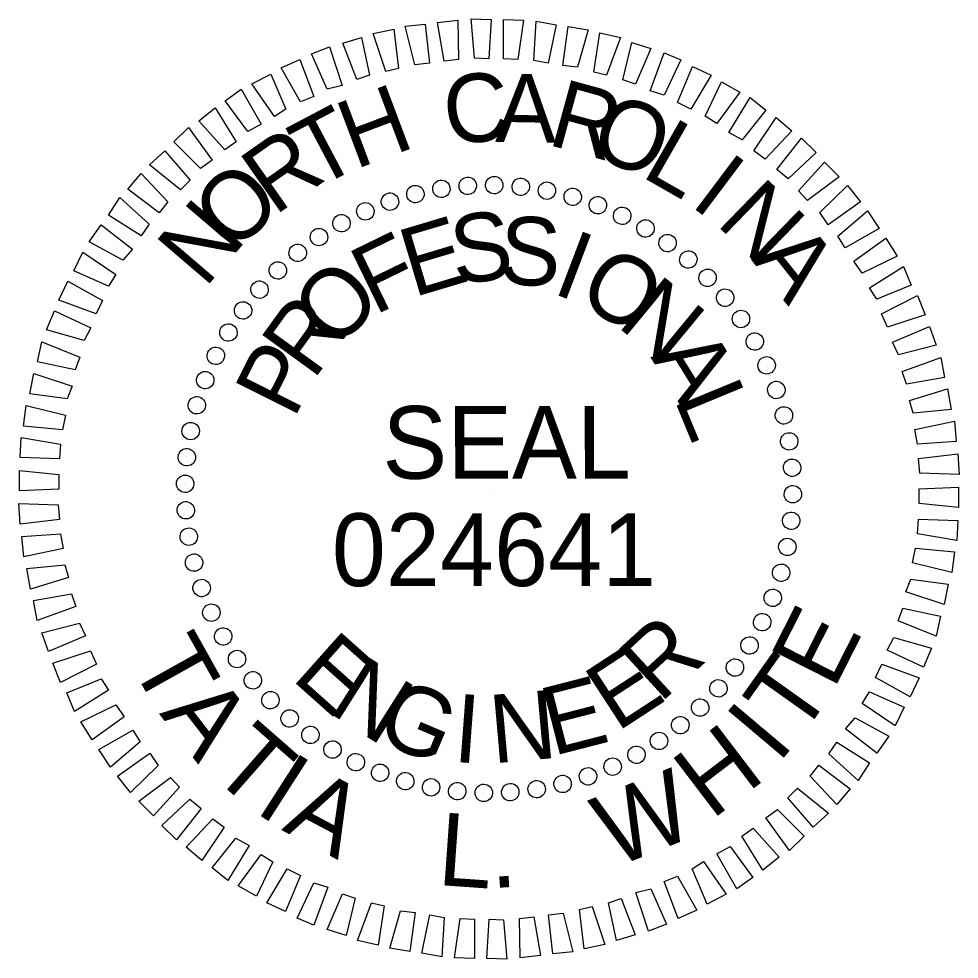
# Model space of a CAD drawing. Extents: x 573468 to 580768, y -57414 to -51768.
# Drawn here: x 580590.4 to 580668, y -53157.1 to -53079.5 of the extents above; entities that cross this region are included whole.
import ezdxf

# ---------------------------------------------------------------- set-up
doc = ezdxf.new("R2010")
doc.units = 0
doc.layers.add('Sheet Professional Seal CELL', color=7, linetype='Continuous')

msp = doc.modelspace()

# ---------------------------------------------------------------- linework, layer by layer
at = {"layer": 'Sheet Professional Seal CELL'}
for p, q in [((580627.458, -53093.227), (580627.458, -53093.227)), ((580629.658, -53093.176), (580629.658, -53093.176)), ((580631.858, -53093.325), (580631.858, -53093.325)), ((580623.108, -53093.928), (580623.108, -53093.928)), ((580625.308, -53093.527), (580625.308, -53093.527)), ((580634.008, -53093.675), (580634.008, -53093.675)), ((580636.108, -53094.124), (580636.108, -53094.124)), ((580621.008, -53094.528), (580621.008, -53094.528)), ((580638.208, -53094.824), (580638.208, -53094.824)), ((580619.008, -53095.329), (580619.008, -53095.329)), ((580640.208, -53095.723), (580640.208, -53095.723)), ((580617.059, -53096.329), (580617.059, -53096.329)), ((580642.159, -53096.723), (580642.159, -53096.723)), ((580615.159, -53097.48), (580615.159, -53097.48)), ((580643.959, -53097.972), (580643.959, -53097.972)), ((580613.409, -53098.73), (580613.409, -53098.73)), ((580645.709, -53099.322), (580645.709, -53099.322)), ((580611.76, -53100.23), (580611.76, -53100.23)), ((580647.26, -53100.822), (580647.26, -53100.822)), ((580610.26, -53101.781), (580610.26, -53101.781)), ((580648.76, -53102.471), (580648.76, -53102.471)), ((580608.91, -53103.531), (580608.91, -53103.531)), ((580650.011, -53104.221), (580650.011, -53104.221)), ((580607.661, -53105.331), (580607.661, -53105.331)), ((580651.161, -53106.121), (580651.161, -53106.121)), ((580606.661, -53107.282), (580606.661, -53107.282)), ((580652.162, -53108.07), (580652.162, -53108.07)), ((580605.762, -53109.282), (580605.762, -53109.282)), ((580652.962, -53110.07), (580652.962, -53110.07)), ((580605.062, -53111.382), (580605.062, -53111.382)), ((580653.563, -53112.17), (580653.563, -53112.17)), ((580604.613, -53113.482), (580604.613, -53113.482)), ((580653.963, -53114.37), (580653.963, -53114.37)), ((580604.263, -53115.632), (580604.263, -53115.632)), ((580654.264, -53116.52), (580654.264, -53116.52)), ((580604.114, -53117.832), (580604.114, -53117.832)), ((580629.214, -53118.276), (580629.214, -53118.276)), ((580654.314, -53118.72), (580654.314, -53118.72)), ((580604.165, -53120.032), (580604.165, -53120.032)), ((580654.165, -53120.92), (580654.165, -53120.92)), ((580604.465, -53122.182), (580604.465, -53122.182)), ((580653.815, -53123.07), (580653.815, -53123.07)), ((580604.866, -53124.382), (580604.866, -53124.382)), ((580653.366, -53125.17), (580653.366, -53125.17)), ((580605.466, -53126.482), (580605.466, -53126.482)), ((580652.666, -53127.27), (580652.666, -53127.27)), ((580606.267, -53128.482), (580606.267, -53128.482)), ((580651.767, -53129.27), (580651.767, -53129.27)), ((580607.267, -53130.432), (580607.267, -53130.432)), ((580650.767, -53131.221), (580650.767, -53131.221)), ((580608.418, -53132.331), (580608.418, -53132.331)), ((580649.518, -53133.021), (580649.518, -53133.021)), ((580609.668, -53134.081), (580609.668, -53134.081)), ((580648.168, -53134.771), (580648.168, -53134.771)), ((580611.168, -53135.731), (580611.168, -53135.731)), ((580646.669, -53136.322), (580646.669, -53136.322)), ((580612.719, -53137.23), (580612.719, -53137.23)), ((580645.019, -53137.822), (580645.019, -53137.822)), ((580614.469, -53138.58), (580614.469, -53138.58)), ((580643.269, -53139.073), (580643.269, -53139.073)), ((580616.27, -53139.829), (580616.27, -53139.829)), ((580618.22, -53140.829), (580618.22, -53140.829)), ((580641.37, -53140.223), (580641.37, -53140.223)), ((580639.42, -53141.224), (580639.42, -53141.224)), ((580620.22, -53141.728), (580620.22, -53141.728)), ((580637.42, -53142.024), (580637.42, -53142.024)), ((580622.32, -53142.428), (580622.32, -53142.428)), ((580624.42, -53142.877), (580624.42, -53142.877)), ((580633.12, -53143.025), (580633.12, -53143.025)), ((580635.32, -53142.625), (580635.32, -53142.625)), ((580626.57, -53143.227), (580626.57, -53143.227)), ((580628.77, -53143.376), (580628.77, -53143.376)), ((580630.97, -53143.326), (580630.97, -53143.326))]:
    msp.add_line(p, q, dxfattribs=at)
for points in [[(580628.005, -53082.726), (580627.754, -53079.476), (580629.404, -53079.526), (580629.205, -53082.776)], [(580630.405, -53082.776), (580630.404, -53079.526), (580632.054, -53079.575), (580631.605, -53082.825)], [(580623.105, -53083.278), (580622.305, -53080.078), (580623.955, -53079.927), (580624.305, -53083.127)], [(580625.505, -53082.977), (580624.955, -53079.777), (580626.654, -53079.577), (580626.705, -53082.827)], [(580632.905, -53082.925), (580633.104, -53079.675), (580634.755, -53079.975), (580634.105, -53083.125)], [(580635.305, -53083.325), (580635.755, -53080.124), (580637.405, -53080.374), (580636.505, -53083.474)], [(580618.306, -53084.479), (580617.155, -53081.479), (580618.705, -53081.029), (580619.356, -53084.129)], [(580620.706, -53083.828), (580619.655, -53080.678), (580621.355, -53080.328), (580621.755, -53083.578)], [(580637.856, -53083.874), (580638.355, -53080.624), (580640.055, -53081.023), (580638.906, -53084.124)], [(580615.856, -53085.279), (580614.555, -53082.38), (580616.055, -53081.779), (580617.106, -53084.979)], [(580640.256, -53084.523), (580641.005, -53081.423), (580642.555, -53081.923), (580641.306, -53084.873)], [(580642.506, -53085.423), (580643.655, -53082.272), (580645.055, -53082.872), (580643.656, -53085.772)], [(580613.656, -53086.33), (580612.055, -53083.53), (580613.605, -53082.83), (580614.756, -53085.88)], [(580611.506, -53087.531), (580609.656, -53084.831), (580611.206, -53084.031), (580612.456, -53086.93)], [(580644.756, -53086.372), (580646.005, -53083.422), (580647.556, -53084.122), (580645.856, -53086.922)], [(580647.056, -53087.522), (580648.406, -53084.671), (580649.906, -53085.521), (580648.007, -53088.121)], [(580609.307, -53088.781), (580607.456, -53086.232), (580608.756, -53085.281), (580610.407, -53088.181)], [(580649.007, -53088.871), (580650.756, -53085.971), (580652.056, -53087.02), (580650.107, -53089.471)], [(580607.407, -53090.282), (580605.257, -53087.882), (580606.606, -53086.832), (580608.357, -53089.631)], [(580651.057, -53090.371), (580652.906, -53087.62), (580654.207, -53088.72), (580652.007, -53091.07)], [(580605.408, -53091.832), (580603.207, -53089.633), (580604.407, -53088.432), (580606.357, -53091.132)], [(580652.958, -53091.92), (580655.007, -53089.32), (580656.207, -53090.519), (580653.908, -53092.67)], [(580603.758, -53093.582), (580601.207, -53091.533), (580602.457, -53090.383), (580604.558, -53092.782)], [(580654.758, -53093.67), (580656.907, -53091.319), (580658.108, -53092.519), (580655.508, -53094.47)], [(580602.008, -53095.483), (580599.408, -53093.534), (580600.508, -53092.233), (580602.708, -53094.583)], [(580656.508, -53095.469), (580658.808, -53093.219), (580659.858, -53094.568), (580657.209, -53096.469)], [(580600.509, -53097.383), (580597.808, -53095.684), (580598.758, -53094.234), (580601.159, -53096.433)], [(580658.009, -53097.419), (580660.458, -53095.318), (580661.409, -53096.768), (580658.609, -53098.369)], [(580599.009, -53099.384), (580596.209, -53097.884), (580597.209, -53096.484), (580599.809, -53098.483)], [(580659.309, -53099.469), (580661.959, -53097.568), (580662.909, -53099.068), (580660.01, -53100.468)], [(580597.81, -53101.534), (580594.96, -53100.285), (580595.709, -53098.734), (580598.41, -53100.584)], [(580660.61, -53101.668), (580663.41, -53099.918), (580664.06, -53101.467), (580661.21, -53102.618)], [(580596.811, -53103.834), (580593.71, -53102.685), (580594.46, -53101.135), (580597.31, -53102.734)], [(580661.611, -53103.818), (580664.56, -53102.317), (580665.211, -53103.917), (580662.111, -53104.918)], [(580595.811, -53106.034), (580592.711, -53105.135), (580593.36, -53103.585), (580596.361, -53104.984)], [(580662.511, -53106.168), (580665.561, -53104.867), (580666.111, -53106.417), (580663.011, -53107.218)], [(580595.062, -53108.435), (580591.962, -53107.785), (580592.311, -53106.135), (580595.461, -53107.385)], [(580663.312, -53108.568), (580666.511, -53107.417), (580666.812, -53109.067), (580663.662, -53109.617)], [(580594.412, -53110.835), (580591.312, -53110.436), (580591.662, -53108.735), (580594.812, -53109.785)], [(580663.912, -53110.967), (580667.062, -53110.017), (580667.362, -53111.717), (580664.213, -53112.017)], [(580594.013, -53113.385), (580590.813, -53113.086), (580591.012, -53111.386), (580594.263, -53112.185)], [(580664.363, -53113.367), (580667.613, -53112.666), (580667.763, -53114.366), (580664.563, -53114.567)], [(580593.764, -53115.785), (580590.513, -53115.686), (580590.613, -53114.036), (580593.863, -53114.585)], [(580664.664, -53115.767), (580667.913, -53115.366), (580668.014, -53117.066), (580664.764, -53116.967)], [(580593.714, -53118.285), (580590.464, -53118.436), (580590.464, -53116.736), (580593.714, -53117.085)], [(580664.714, -53118.267), (580667.964, -53118.116), (580667.965, -53119.816), (580664.714, -53119.467)], [(580593.765, -53120.785), (580590.515, -53121.186), (580590.414, -53119.486), (580593.664, -53119.585)], [(580664.665, -53120.767), (580667.915, -53120.866), (580667.815, -53122.516), (580664.565, -53121.967)], [(580594.065, -53123.185), (580590.816, -53123.886), (580590.665, -53122.186), (580593.865, -53121.985)], [(580664.415, -53123.167), (580667.615, -53123.466), (580667.416, -53125.167), (580664.166, -53124.367)], [(580594.516, -53125.585), (580591.366, -53126.536), (580591.066, -53124.836), (580594.216, -53124.535)], [(580664.016, -53125.717), (580667.116, -53126.117), (580666.767, -53127.817), (580663.616, -53126.767)], [(580595.117, -53127.985), (580591.917, -53129.135), (580591.616, -53127.485), (580594.766, -53126.935)], [(580663.367, -53128.118), (580666.467, -53128.767), (580666.117, -53130.417), (580662.967, -53129.168)], [(580595.917, -53130.384), (580592.867, -53131.685), (580592.317, -53130.135), (580595.417, -53129.335)], [(580662.617, -53130.518), (580665.717, -53131.417), (580665.068, -53132.967), (580662.067, -53131.568)], [(580596.818, -53132.734), (580593.868, -53134.235), (580593.218, -53132.635), (580596.317, -53131.634)], [(580661.618, -53132.718), (580664.718, -53133.867), (580663.968, -53135.417), (580661.118, -53133.818)], [(580597.818, -53134.884), (580595.019, -53136.635), (580594.368, -53135.085), (580597.218, -53133.934)], [(580660.618, -53135.018), (580663.469, -53136.268), (580662.719, -53137.818), (580660.019, -53135.968)], [(580599.119, -53137.084), (580596.469, -53138.984), (580595.519, -53137.485), (580598.419, -53136.084)], [(580659.419, -53137.169), (580662.219, -53138.668), (580661.22, -53140.068), (580658.619, -53138.069)], [(580600.419, -53139.133), (580597.97, -53141.234), (580597.02, -53139.784), (580599.819, -53138.183)], [(580657.919, -53139.169), (580660.62, -53140.868), (580659.67, -53142.318), (580657.27, -53140.119)], [(580601.92, -53141.083), (580599.62, -53143.333), (580598.57, -53141.984), (580601.22, -53140.083)], [(580656.42, -53141.069), (580659.02, -53143.019), (580657.921, -53144.319), (580655.72, -53141.969)], [(580603.67, -53142.882), (580601.521, -53145.233), (580600.321, -53144.033), (580602.92, -53142.083)], [(580654.67, -53142.97), (580657.221, -53145.019), (580655.971, -53146.169), (580653.871, -53143.77)], [(580605.471, -53144.632), (580603.421, -53147.233), (580602.221, -53146.033), (580604.521, -53143.882)], [(580653.021, -53144.72), (580655.221, -53146.92), (580654.022, -53148.12), (580652.071, -53145.42)], [(580607.371, -53146.182), (580605.522, -53148.932), (580604.222, -53147.832), (580606.421, -53145.482)], [(580651.021, -53146.271), (580653.172, -53148.67), (580651.822, -53149.72), (580650.071, -53146.921)], [(580609.421, -53147.681), (580607.672, -53150.581), (580606.372, -53149.532), (580608.321, -53147.081)], [(580649.122, -53147.771), (580650.972, -53150.321), (580649.672, -53151.271), (580648.022, -53148.371)], [(580611.372, -53149.031), (580610.023, -53151.881), (580608.522, -53151.031), (580610.422, -53148.431)], [(580646.922, -53149.022), (580648.772, -53151.721), (580647.223, -53152.522), (580645.972, -53149.622)], [(580613.672, -53150.18), (580612.423, -53153.13), (580610.873, -53152.431), (580612.572, -53149.63)], [(580615.922, -53151.129), (580614.773, -53154.28), (580613.373, -53153.68), (580614.772, -53150.78)], [(580644.772, -53150.222), (580646.373, -53153.022), (580644.823, -53153.722), (580643.672, -53150.672)], [(580618.173, -53152.029), (580617.423, -53155.129), (580615.873, -53154.629), (580617.122, -53151.679)], [(580642.572, -53151.273), (580643.873, -53154.172), (580642.373, -53154.773), (580641.322, -53151.573)], [(580620.573, -53152.678), (580620.074, -53155.928), (580618.373, -53155.529), (580619.523, -53152.429)], [(580640.123, -53152.073), (580641.273, -53155.073), (580639.723, -53155.523), (580639.073, -53152.424)], [(580623.123, -53153.228), (580622.674, -53156.428), (580621.024, -53156.178), (580621.923, -53153.078)], [(580637.723, -53152.724), (580638.774, -53155.874), (580637.074, -53156.224), (580636.673, -53152.974)], [(580625.523, -53153.627), (580625.324, -53156.877), (580623.674, -53156.577), (580624.323, -53153.427)], [(580628.023, -53153.776), (580628.024, -53157.026), (580626.374, -53156.977), (580626.823, -53153.727)], [(580630.423, -53153.826), (580630.674, -53157.076), (580629.024, -53157.026), (580629.223, -53153.776)], [(580632.923, -53153.575), (580633.474, -53156.775), (580631.774, -53156.975), (580631.723, -53153.725)], [(580635.323, -53153.275), (580636.124, -53156.474), (580634.474, -53156.625), (580634.123, -53153.425)]]:
    msp.add_lwpolyline(points, close=True, dxfattribs=at)
for centre, major_axis in [((580627.458, -53093.258), (-0.05, 0.718)), ((580629.646, -53093.2), (0.012, 0.72)), ((580631.829, -53093.333), (0.075, 0.716)), ((580623.141, -53093.943), (-0.174, 0.699)), ((580625.285, -53093.506), (-0.113, 0.711)), ((580633.993, -53093.656), (0.137, 0.707)), ((580636.121, -53094.166), (0.198, 0.692)), ((580621.043, -53094.565), (-0.235, 0.681)), ((580638.196, -53094.86), (0.258, 0.672)), ((580619.007, -53095.367), (-0.293, 0.658)), ((580640.203, -53095.732), (0.315, 0.647)), ((580617.05, -53096.344), (-0.349, 0.63)), ((580642.126, -53096.775), (0.371, 0.617)), ((580615.184, -53097.487), (-0.403, 0.597)), ((580643.951, -53097.982), (0.423, 0.583)), ((580613.426, -53098.789), (-0.453, 0.559)), ((580645.663, -53099.344), (0.472, 0.544)), ((580611.788, -53100.239), (-0.5, 0.518)), ((580647.251, -53100.85), (0.518, 0.5)), ((580610.282, -53101.827), (-0.544, 0.472)), ((580648.701, -53102.488), (0.559, 0.453)), ((580608.92, -53103.54), (-0.583, 0.423)), ((580650.003, -53104.246), (0.597, 0.403)), ((580607.713, -53105.364), (-0.617, 0.371)), ((580651.147, -53106.112), (0.63, 0.349)), ((580606.67, -53107.287), (-0.647, 0.315)), ((580652.123, -53108.069), (0.658, 0.293)), ((580605.798, -53109.294), (-0.672, 0.258)), ((580652.926, -53110.105), (0.681, 0.235)), ((580605.104, -53111.369), (-0.692, 0.198)), ((580653.548, -53112.203), (0.699, 0.174)), ((580604.594, -53113.497), (-0.707, 0.137)), ((580653.984, -53114.347), (0.711, 0.113)), ((580604.271, -53115.661), (-0.716, 0.075)), ((580654.233, -53116.52), (0.718, 0.05)), ((580604.138, -53117.845), (-0.72, 0.012)), ((580654.29, -53118.708), (0.72, -0.012)), ((580604.196, -53120.032), (-0.718, -0.05)), ((580654.157, -53120.891), (0.716, -0.075)), ((580604.444, -53122.206), (-0.711, -0.113)), ((580653.835, -53123.055), (0.707, -0.137)), ((580604.881, -53124.35), (-0.699, -0.174)), ((580653.324, -53125.183), (0.692, -0.198)), ((580605.503, -53126.447), (-0.681, -0.235)), ((580652.631, -53127.258), (0.672, -0.258)), ((580606.305, -53128.483), (-0.658, -0.293)), ((580651.759, -53129.265), (0.647, -0.315)), ((580607.282, -53130.441), (-0.63, -0.349)), ((580650.715, -53131.188), (0.617, -0.371)), ((580608.425, -53132.306), (-0.597, -0.403)), ((580649.508, -53133.013), (0.583, -0.423)), ((580609.727, -53134.064), (-0.559, -0.453)), ((580648.146, -53134.725), (0.544, -0.472)), ((580611.177, -53135.703), (-0.518, -0.5)), ((580646.641, -53136.313), (0.5, -0.518)), ((580612.765, -53137.208), (-0.472, -0.544)), ((580645.002, -53137.763), (0.453, -0.559)), ((580614.478, -53138.57), (-0.423, -0.583)), ((580643.244, -53139.065), (0.403, -0.597)), ((580616.302, -53139.777), (-0.371, -0.617)), ((580618.225, -53140.821), (-0.315, -0.647)), ((580641.379, -53140.209), (0.349, -0.63)), ((580639.421, -53141.185), (0.293, -0.658)), ((580620.232, -53141.693), (-0.258, -0.672)), ((580622.307, -53142.386), (-0.198, -0.692)), ((580637.385, -53141.988), (0.235, -0.681)), ((580624.435, -53142.896), (-0.137, -0.707)), ((580633.144, -53143.046), (0.113, -0.711)), ((580635.288, -53142.61), (0.174, -0.699)), ((580626.599, -53143.219), (-0.075, -0.716)), ((580628.783, -53143.352), (-0.012, -0.72)), ((580630.97, -53143.295), (0.05, -0.718))]:
    msp.add_ellipse(centre, major_axis=major_axis, ratio=0.999708, dxfattribs=at)

# ---------------------------------------------------------------- texts
for s, height, rotation, p in [('C', 5.638, 6.23419, (580625.757, -53089.927)), ('A', 5.638, 359.03464, (580629.707, -53089.626)), ('H', 5.638, 20.6338, (580618.158, -53091.929)), ('R', 5.638, 344.63542, (580633.907, -53089.825)), ('O', 5.638, 337.43548, (580637.257, -53090.574)), ('T', 5.638, 27.83409, (580614.908, -53093.58)), ('L', 5.638, 330.23519, (580641.658, -53092.423)), ('R', 5.639, 35.03482, (580611.509, -53095.781)), ('I', 5.638, 323.03446, (580645.708, -53094.822)), ('O', 5.638, 42.23606, (580608.059, -53098.881)), ('N', 5.639, 315.83323, (580647.859, -53096.371)), ('N', 5.639, 49.43782, (580605.76, -53101.782)), ('E', 5.638, 16.62539, (580622.96, -53102.478)), ('S', 5.638, 7.26993, (580626.41, -53101.427)), ('S', 5.638, 357.91472, (580630.01, -53101.376)), ('F', 5.638, 25.98135, (580619.761, -53103.978)), ('I', 5.638, 339.20392, (580634.31, -53102.075)), ('A', 5.639, 308.63147, (580650.809, -53099.321)), ('O', 5.638, 329.8478, (580636.31, -53102.774)), ('O', 5.639, 44.69556, (580616.461, -53106.929)), ('N', 5.638, 320.49093, (580639.661, -53104.773)), ('R', 5.639, 54.05397, (580614.712, -53109.38)), ('P', 5.639, 63.41321, (580613.113, -53112.58)), ('A', 5.639, 301.77459, (580642.511, -53107.373)), ('L', 5.639, 292.41517, (580644.462, -53110.822)), ('SEAL', 5.9982, 0.01432, (580620.415, -53117.43)), ('024641', 5.9982, 0.01432, (580616.245, -53126.288)), ('E', 5.998, 63.13321, (580657.651, -53134.924)), ('R', 5.639, 42.49573, (580643.319, -53136.023)), ('T', 5.998, 299.17946, (580599.522, -53132.566)), ('E', 5.638, 318.29121, (580612.818, -53133.93)), ('E', 5.638, 33.13841, (580639.769, -53138.373)), ('N', 5.638, 327.64827, (580615.819, -53136.629)), ('T', 5.998, 54.61139, (580654.87, -53138.954)), ('E', 5.638, 14.42608, (580634.47, -53140.325)), ('G', 5.638, 337.00456, (580619.619, -53138.878)), ('A', 5.998, 307.70128, (580601.968, -53136.808)), ('I', 5.638, 355.71552, (580626.17, -53140.777)), ('N', 5.638, 5.07071, (580629.52, -53140.926)), ('I', 5.998, 49.84692, (580653.064, -53141.014)), ('T', 5.998, 318.77965, (580606.036, -53141.698)), ('H', 5.998, 37.33533, (580647.571, -53145.64)), ('I', 5.998, 327.30147, (580609.763, -53144.874)), ('W', 5.998, 21.62807, (580639.478, -53149.588)), ('A', 5.998, 332.06594, (580612.04, -53146.398)), ('L', 5.998, 355.92704, (580624.883, -53150.942)), ('.', 5.998, 3.79035, (580629.393, -53151.227))]:
    msp.add_text(s, height=height, rotation=rotation, dxfattribs=at).set_placement(p)

doc.saveas('drawing.dxf')
